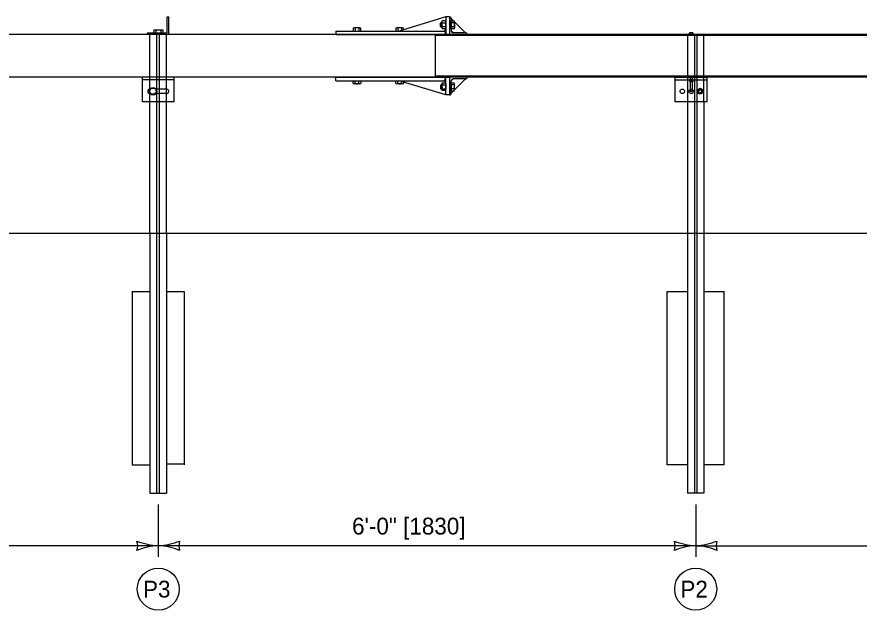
# Model space of a CAD drawing. Extents: x 49991.4 to 50021, y 49987.6 to 50011.4.
# Drawn here: x 50010.735 to 50013.742, y 49993.08 to 49995.198 of the extents above; entities that cross this region are included whole.
import ezdxf

# ---------------------------------------------------------------- set-up
doc = ezdxf.new("R2010")
doc.units = 0
for name, color, linetype in [('Level 1', 7, 'Continuous'), ('Level 2', 7, 'Continuous'), ('Level 3', 7, 'Continuous'), ('Level 4', 7, 'Continuous'), ('Level 63', 7, 'Continuous')]:
    doc.layers.add(name, color=color, linetype=linetype)

# ---------------------------------------------------------------- blocks, each defined once
blk = doc.blocks.new('HEX$NU')
at = {"layer": 'Level 63'}
for p, q in [((0, -0.325), (0, 0.325)), ((0.03, 0.433), (0.418, 0.433)), ((0.03, 0.216), (0.418, 0.216)), ((0.448, 0.325), (0.448, -0.325)), ((0.03, -0.216), (0.418, -0.216)), ((0.418, -0.433), (0.03, -0.433))]:
    blk.add_line(p, q, dxfattribs=at)
for centre, radius, start, end in [((0.21, 0.325), 0.21, 149.0201, 210.9799), ((0.796, 0), 0.796, 164.2217, 195.7782), ((0.238, 0.325), 0.21, 329.0201, 30.97992), ((-0.348, 0), 0.796, 344.2218, 15.77825), ((0.21, -0.325), 0.21, 149.0201, 210.9799), ((0.238, -0.325), 0.21, 329.0201, 30.97991)]:
    blk.add_arc(centre, radius, start, end, dxfattribs=at)
blk = doc.blocks.new('HEX$BO')
at = {"layer": 'Level 63'}
blk.add_lwpolyline([(0, 0.433), (-0.375, 0.2165), (-0.375, -0.2165), (0, -0.433), (0.375, -0.2165), (0.375, 0.2165)], close=True, dxfattribs=at)
blk.add_circle((0, 0), 0.25, dxfattribs=at)
for start, end in [(167.0572, 187.9055), (127.03, 148.675), (91.36985, 104.7376), (62.329189, 72.366658), (18.86795, 41.261061), (207.6209, 226.5812), (247.4266, 272.6797), (298.2529, 323.1939), (337.4806, 357.0806)]:
    blk.add_arc((0, 0), 0.2226, start, end, dxfattribs=at)

msp = doc.modelspace()

# ---------------------------------------------------------------- linework, layer by layer
at = {"layer": 'Level 1'}
for p, q in [((50011.2712, 49995.1981), (50011.2776, 49995.1981)), ((50011.2712, 49995.1411), (50011.2712, 49995.1981)), ((50011.2776, 49995.1348), (50011.2776, 49995.1981)), ((50012.2668, 49995.1981), (50012.1002, 49995.1474)), ((50012.2668, 49995.1981), (50012.2668, 49995.1348)), ((50012.2795, 49995.1981), (50012.2668, 49995.1981)), ((50012.2795, 49995.1981), (50012.2795, 49995.1348)), ((50012.2795, 49995.1981), (50012.2795, 49995.1981)), ((50012.2795, 49995.1981), (50012.2795, 49995.1981)), ((50012.2859, 49995.1917), (50012.3366, 49995.1411)), ((50012.2859, 49995.1917), (50012.2859, 49995.1474)), ((50011.2242, 49995.1523), (50011.2554, 49995.1523)), ((50011.2242, 49995.1523), (50011.2242, 49995.1411)), ((50011.231, 49995.1523), (50011.231, 49995.1411)), ((50011.2486, 49995.1523), (50011.2486, 49995.1411)), ((50011.2554, 49995.1523), (50011.2554, 49995.1411)), ((50011.9598, 49995.159), (50011.9392, 49995.159)), ((50011.9426, 49995.1579), (50011.9426, 49995.1474)), ((50011.9426, 49995.1579), (50011.9426, 49995.1474)), ((50011.9563, 49995.1579), (50011.9563, 49995.1474)), ((50012.1121, 49995.159), (50012.0915, 49995.159)), ((50012.1121, 49995.159), (50012.0915, 49995.159)), ((50012.0949, 49995.1579), (50012.0949, 49995.1474)), ((50012.0949, 49995.1579), (50012.0949, 49995.1474)), ((50012.1087, 49995.1579), (50012.1087, 49995.15)), ((50012.1087, 49995.1579), (50012.1087, 49995.15)), ((50012.1155, 49995.1521), (50012.1155, 49995.1579)), ((50012.1155, 49995.1521), (50012.1155, 49995.1579)), ((50012.2494, 49995.1775), (50012.2478, 49995.1759)), ((50012.2478, 49995.1633), (50012.2478, 49995.1759)), ((50012.2494, 49995.1617), (50012.2478, 49995.1633)), ((50012.2494, 49995.1775), (50012.2494, 49995.1617)), ((50012.2494, 49995.1775), (50012.2526, 49995.1775)), ((50012.2526, 49995.1759), (50012.2494, 49995.1759)), ((50012.2494, 49995.1633), (50012.2526, 49995.1633)), ((50012.2526, 49995.1617), (50012.2494, 49995.1617)), ((50012.2668, 49995.1538), (50012.2605, 49995.1474)), ((50012.2963, 49995.1764), (50012.2859, 49995.1764)), ((50012.2963, 49995.1627), (50012.2859, 49995.1627)), ((50012.2974, 49995.1799), (50012.2974, 49995.1593)), ((50012.2287, 49995.1348), (50001.2264, 49995.1348)), ((50011.2016, 49995.1348), (50011.2016, 49995.1411)), ((50011.2016, 49995.1411), (50011.2712, 49995.1411)), ((50011.8733, 49995.1474), (50011.8733, 49995.1348)), ((50011.8733, 49995.1474), (50012.2605, 49995.1474)), ((50011.8733, 49995.1348), (50012.2605, 49995.1348)), ((50015.8847, 49995.1348), (50012.2287, 49995.1348)), ((50012.2287, 49995.1348), (50012.2287, 49994.9829)), ((50012.2287, 49995.1348), (50012.2287, 49994.9829)), ((50012.2605, 49995.1474), (50012.2668, 49995.1411)), ((50012.2605, 49995.1348), (50012.2668, 49995.1411)), ((50012.2668, 49995.1348), (50012.2795, 49995.1348)), ((50012.343, 49995.1348), (50012.2795, 49995.1348)), ((50012.2922, 49995.1411), (50012.2859, 49995.1474)), ((50012.3366, 49995.1411), (50012.2922, 49995.1411)), ((50012.343, 49995.1348), (50012.343, 49995.1348)), ((50013.1479, 49995.1405), (50013.1376, 49995.1405)), ((50013.1479, 49995.1405), (50013.1376, 49995.1405)), ((50013.1393, 49995.14), (50013.1393, 49995.1348)), ((50013.1393, 49995.14), (50013.1393, 49995.1348)), ((50013.1462, 49995.14), (50013.1462, 49995.1348)), ((50013.1462, 49995.14), (50013.1462, 49995.1348)), ((50012.2287, 49994.9829), (50001.2264, 49994.9829)), ((50011.1828, 49994.8944), (50011.1828, 49994.9829)), ((50011.2968, 49994.9734), (50011.1828, 49994.9734)), ((50011.2968, 49994.8944), (50011.2968, 49994.9829)), ((50011.8733, 49994.9829), (50012.2605, 49994.9829)), ((50011.8733, 49994.9702), (50011.8733, 49994.9829)), ((50015.4023, 49994.9829), (50012.2287, 49994.9829)), ((50012.2605, 49994.9829), (50012.2668, 49994.9766)), ((50012.2605, 49994.9702), (50012.2668, 49994.9766)), ((50012.2668, 49994.9829), (50012.2795, 49994.9829)), ((50012.2668, 49994.9196), (50012.2668, 49994.9829)), ((50012.343, 49994.9829), (50012.2795, 49994.9829)), ((50012.2795, 49994.9829), (50012.2795, 49994.9196)), ((50012.2922, 49994.9766), (50012.2859, 49994.9702)), ((50012.2859, 49994.9259), (50012.3366, 49994.9766)), ((50012.3366, 49994.9766), (50012.2922, 49994.9766)), ((50012.343, 49994.9829), (50012.343, 49994.9829)), ((50013.0856, 49994.8943), (50013.0856, 49994.9829)), ((50013.0856, 49994.9829), (50013.1999, 49994.9829)), ((50013.0856, 49994.9734), (50013.1999, 49994.9734)), ((50013.1388, 49994.9829), (50013.1467, 49994.9829)), ((50013.1388, 49994.9829), (50013.1467, 49994.9829)), ((50013.1396, 49994.933), (50013.1396, 49994.9829)), ((50013.1459, 49994.9829), (50013.1459, 49994.933)), ((50013.1999, 49994.8943), (50013.1999, 49994.9829)), ((50011.8733, 49994.9702), (50012.2605, 49994.9702)), ((50011.9598, 49994.9587), (50011.9392, 49994.9587)), ((50011.9598, 49994.9587), (50011.9392, 49994.9587)), ((50011.9426, 49994.9598), (50011.9426, 49994.9702)), ((50011.9426, 49994.9598), (50011.9426, 49994.9702)), ((50011.9563, 49994.9598), (50011.9563, 49994.9702)), ((50011.9563, 49994.9598), (50011.9563, 49994.9702)), ((50012.1121, 49994.9587), (50012.0915, 49994.9587)), ((50012.0949, 49994.9598), (50012.0949, 49994.9702)), ((50012.0949, 49994.9598), (50012.0949, 49994.9702)), ((50012.2668, 49994.9196), (50012.1002, 49994.9702)), ((50012.1087, 49994.9598), (50012.1087, 49994.9677)), ((50012.1087, 49994.9598), (50012.1087, 49994.9677)), ((50012.1155, 49994.9656), (50012.1155, 49994.9598)), ((50012.1155, 49994.9656), (50012.1155, 49994.9598)), ((50012.2494, 49994.956), (50012.2478, 49994.9544)), ((50012.2478, 49994.9544), (50012.2478, 49994.9417)), ((50012.2494, 49994.9402), (50012.2478, 49994.9417)), ((50012.2494, 49994.9402), (50012.2494, 49994.956)), ((50012.2526, 49994.956), (50012.2494, 49994.956)), ((50012.2494, 49994.9544), (50012.2526, 49994.9544)), ((50012.2526, 49994.9417), (50012.2494, 49994.9417)), ((50012.2668, 49994.9639), (50012.2605, 49994.9702)), ((50012.2859, 49994.9259), (50012.2859, 49994.9702)), ((50012.2963, 49994.9549), (50012.2859, 49994.9549)), ((50012.2974, 49994.9378), (50012.2974, 49994.9584)), ((50013.1388, 49994.9663), (50013.1388, 49994.933)), ((50013.1467, 49994.933), (50013.1467, 49994.9663)), ((50011.2692, 49994.9402), (50011.2316, 49994.9402)), ((50011.2698, 49994.9244), (50011.2318, 49994.9244)), ((50012.2494, 49994.9402), (50012.2526, 49994.9402)), ((50012.2795, 49994.9196), (50012.2668, 49994.9196)), ((50012.2795, 49994.9196), (50012.2795, 49994.9196)), ((50012.2795, 49994.9196), (50012.2795, 49994.9196)), ((50012.2963, 49994.9412), (50012.2859, 49994.9412)), ((50013.1388, 49994.933), (50013.1396, 49994.9323)), ((50013.1388, 49994.933), (50013.1396, 49994.9323)), ((50013.1467, 49994.933), (50013.1388, 49994.933)), ((50013.1467, 49994.933), (50013.1388, 49994.933)), ((50013.1396, 49994.9323), (50013.1459, 49994.9323)), ((50013.1396, 49994.9323), (50013.1459, 49994.9323)), ((50013.1467, 49994.933), (50013.1459, 49994.9323)), ((50013.1467, 49994.933), (50013.1459, 49994.9323)), ((50011.2968, 49994.8944), (50011.1828, 49994.8944)), ((50011.21, 49994.4258), (50011.21, 49994.8943)), ((50011.2692, 49994.4258), (50011.2692, 49994.8943)), ((50013.1999, 49994.8943), (50013.0856, 49994.8943)), ((50013.129, 49994.8943), (50013.129, 49994.4259)), ((50013.1882, 49994.8943), (50013.1882, 49994.4259)), ((49999.8098, 49994.4259), (50016.5942, 49994.4259))]:
    msp.add_line(p, q, dxfattribs=at)
for points in [[(50012.2963, 49995.1559), (50012.2859, 49995.1559), (50012.2859, 49995.1833), (50012.2963, 49995.1833)], [(50011.9357, 49995.1579), (50011.9357, 49995.1474), (50011.9632, 49995.1474), (50011.9632, 49995.1579)], [(50011.9357, 49995.1579), (50011.9357, 49995.1474), (50011.9632, 49995.1474), (50011.9632, 49995.1579)], [(50012.088, 49995.1579), (50012.088, 49995.1474), (50012.1002, 49995.1474)], [(50012.088, 49995.1579), (50012.088, 49995.1474), (50012.1002, 49995.1474)], [(50013.1359, 49995.14), (50013.1359, 49995.1348), (50013.1496, 49995.1348), (50013.1496, 49995.14)], [(50013.1359, 49995.14), (50013.1359, 49995.1348), (50013.1496, 49995.1348), (50013.1496, 49995.14)], [(50011.9357, 49994.9598), (50011.9357, 49994.9702), (50011.9632, 49994.9702), (50011.9632, 49994.9598)], [(50011.9357, 49994.9598), (50011.9357, 49994.9702), (50011.9632, 49994.9702), (50011.9632, 49994.9598)], [(50012.088, 49994.9598), (50012.088, 49994.9702), (50012.1002, 49994.9702)], [(50012.088, 49994.9598), (50012.088, 49994.9702), (50012.1002, 49994.9702)], [(50012.2963, 49994.9618), (50012.2859, 49994.9618), (50012.2859, 49994.9344), (50012.2963, 49994.9344)]]:
    msp.add_lwpolyline(points, dxfattribs=at)
msp.add_lwpolyline([(50011.2146, 49994.9431), (50011.227, 49994.943), (50011.233, 49994.9322), (50011.2266, 49994.9216), (50011.2144, 49994.9218), (50011.2084, 49994.9325)], close=True, dxfattribs=at)
msp.add_circle((50011.2208, 49994.9322), 0.0135, dxfattribs=at)
for centre, start, end in [((50011.2097, 49994.9323), 88.9909, 270.2781), ((50011.2698, 49994.9323), 269.7219, 91.0091)]:
    msp.add_arc(centre, 0.00794, start, end, dxfattribs=at)
for centre, major_axis, start_param, end_param in [((50012.2795, 49995.1917), (-0.00635, 0), 3.141593, 4.712389), ((50012.2915, 49995.1799), (-0.00587, 0), 2.516161, 3.767024), ((50011.9392, 49995.1531), (-0.00587, 0), 4.086959, 5.337819), ((50011.9392, 49995.1531), (-0.00587, 0), 4.086959, 5.337819), ((50011.9495, 49995.1372), (-0.0218, 0), 4.391838, 5.03294), ((50011.9495, 49995.1372), (-0.0218, 0), 4.391838, 5.03294), ((50011.9598, 49995.1531), (-0.00587, 0), 4.086957, 5.337821), ((50012.0915, 49995.1531), (-0.00587, 0), 4.086959, 5.337819), ((50012.0915, 49995.1531), (-0.00587, 0), 4.086959, 5.337819), ((50012.1018, 49995.1372), (-0.0218, 0), 4.391838, 5.03294), ((50012.1018, 49995.1372), (-0.0218, 0), 4.391838, 5.03294), ((50012.1121, 49995.1531), (-0.00587, 0), 4.086957, 5.337821), ((50012.1121, 49995.1531), (-0.00587, 0), 4.086957, 5.337821), ((50012.2756, 49995.1696), (-0.0218, 0), 2.821042, 3.462143), ((50012.2915, 49995.1593), (-0.00587, 0), 2.516163, 3.767023), ((50012.2922, 49995.1474), (-0.00635, 0), 0, 1.570796), ((50012.3366, 49995.1348), (-0.00635, 0), 3.141593, 4.712389), ((50013.1376, 49995.1376), (-0.00293, 0), 4.086959, 5.337819), ((50013.1376, 49995.1376), (-0.00293, 0), 4.086959, 5.337819), ((50013.1427, 49995.1297), (-0.0109, 0), 4.391838, 5.03294), ((50013.1427, 49995.1297), (-0.0109, 0), 4.391838, 5.03294), ((50013.1479, 49995.1376), (-0.00293, 0), 4.086957, 5.337821), ((50013.1479, 49995.1376), (-0.00293, 0), 4.086957, 5.337821), ((50012.2922, 49994.9702), (-0.00635, 0), 4.712389, 6.283185), ((50012.3366, 49994.9829), (-0.00635, 0), 1.570796, 3.141593), ((50011.9392, 49994.9646), (-0.00587, 0), 0.945366, 2.196226), ((50011.9392, 49994.9646), (-0.00587, 0), 0.945366, 2.196226), ((50011.9495, 49994.9805), (-0.0218, 0), 1.250246, 1.891347), ((50011.9598, 49994.9646), (-0.00587, 0), 0.945365, 2.196228), ((50011.9598, 49994.9646), (-0.00587, 0), 0.945365, 2.196228), ((50012.0915, 49994.9646), (-0.00587, 0), 0.945366, 2.196226), ((50012.1018, 49994.9805), (-0.0218, 0), 1.250246, 1.891347), ((50012.1018, 49994.9805), (-0.0218, 0), 1.250246, 1.891347), ((50012.1121, 49994.9646), (-0.00587, 0), 0.945365, 2.196228), ((50012.1121, 49994.9646), (-0.00587, 0), 0.945365, 2.196228), ((50012.2915, 49994.9584), (-0.00587, 0), 2.516163, 3.767023), ((50012.2756, 49994.9481), (-0.0218, 0), 2.821042, 3.462143), ((50012.2795, 49994.9259), (-0.00635, 0), 1.570796, 3.141593), ((50012.2915, 49994.9378), (-0.00587, 0), 2.516161, 3.767024)]:
    msp.add_ellipse(centre, major_axis=major_axis, ratio=0.997137, start_param=start_param, end_param=end_param, dxfattribs=at)
for centre in [(50013.111, 49994.9323), (50013.1427, 49994.9323), (50013.1745, 49994.9323)]:
    msp.add_ellipse(centre, major_axis=(-0.00793, 0), ratio=0.997137, dxfattribs=at)
at = {"layer": 'Level 2'}
for centre in [(50011.2397, 49993.1553), (50013.1586, 49993.1553)]:
    msp.add_circle(centre, 0.075, dxfattribs=at)
at = {"layer": 'Level 3'}
for p, q in [((50011.2396, 49993.458), (50011.2396, 49993.2703)), ((50013.1586, 49993.458), (50013.1586, 49993.2703)), ((50011.2396, 49993.3103), (50009.4164, 49993.3103)), ((50013.1586, 49993.3103), (50011.2396, 49993.3103)), ((50013.1586, 49993.3103), (50015.7531, 49993.3103))]:
    msp.add_line(p, q, dxfattribs=at)
for centre, radius, start, end in [((50011.2488, 49993.5324), 0.2223, 247.456, 267.6395), ((50011.1114, 49993.3103), 0.0548, 342.1388, 17.8612), ((50011.2281, 49993.543), 0.233, 272.8273, 292.0772), ((50011.3678, 49993.3103), 0.0548, 162.1388, 197.8612), ((50013.1678, 49993.5324), 0.2223, 247.456, 267.6395), ((50013.0304, 49993.3103), 0.0548, 342.1388, 17.8612), ((50013.1471, 49993.543), 0.233, 272.8273, 292.0772), ((50013.2868, 49993.3103), 0.0548, 162.1388, 197.8612), ((50011.2511, 49993.0776), 0.233, 92.8273, 112.0772), ((50011.2304, 49993.0882), 0.2223, 67.456, 87.6395), ((50013.1701, 49993.0776), 0.233, 92.8273, 112.0772), ((50013.1494, 49993.0882), 0.2223, 67.456, 87.6395)]:
    msp.add_arc(centre, radius, start, end, dxfattribs=at)
at = {"layer": 'Level 4'}
for p, q in [((50011.21, 49994.8944), (50011.21, 49995.1348)), ((50011.235, 49993.498), (50011.235, 49995.1348)), ((50011.2442, 49993.498), (50011.2442, 49995.1348)), ((50011.2692, 49994.8944), (50011.2692, 49995.1348)), ((50015.8847, 49995.1316), (50012.2287, 49995.1316)), ((50013.129, 49995.1348), (50013.129, 49994.8943)), ((50013.154, 49995.1348), (50013.154, 49993.498)), ((50013.1632, 49995.1348), (50013.1632, 49993.498)), ((50013.1882, 49994.8943), (50013.1882, 49995.1348)), ((50015.8847, 49994.986), (50012.2287, 49994.986)), ((50011.21, 49994.4258), (50011.21, 49993.498)), ((50011.2692, 49994.4258), (50011.2692, 49993.498)), ((50013.129, 49994.4259), (50013.129, 49993.498)), ((50013.1882, 49994.4259), (50013.1882, 49993.498)), ((50011.1468, 49994.2178), (50011.21, 49994.2178)), ((50011.1468, 49994.2178), (50011.1468, 49993.5993)), ((50011.2692, 49994.2178), (50011.3324, 49994.2178)), ((50011.3324, 49994.2178), (50011.3324, 49993.5993)), ((50013.057, 49993.5993), (50013.057, 49994.2178)), ((50013.057, 49994.2178), (50013.129, 49994.2178)), ((50013.1882, 49994.2178), (50013.2602, 49994.2178)), ((50013.2602, 49993.5993), (50013.2602, 49994.2178)), ((50011.1468, 49993.5993), (50011.21, 49993.5993)), ((50011.2692, 49993.6027), (50011.3324, 49993.6027)), ((50013.129, 49993.5993), (50013.057, 49993.5993)), ((50013.2602, 49993.5993), (50013.1882, 49993.5993)), ((50011.21, 49993.498), (50011.2692, 49993.498)), ((50013.1882, 49993.498), (50013.129, 49993.498)), ((50013.1632, 49993.5055), (50013.1632, 49993.5055))]:
    msp.add_line(p, q, dxfattribs=at)

# ---------------------------------------------------------------- block references
at = {"layer": 'Level 1', "xscale": 0.031736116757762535}
for p, yscale in [((50012.2527, 49995.1701), -0.031645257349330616), ((50012.2527, 49994.9485), 0.031645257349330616)]:
    msp.add_blockref('HEX$NU', p, dxfattribs=dict(at, yscale=yscale))
at = {"layer": 'Level 1'}
for name, p, xscale, yscale, rotation in [('HEX$NU', (50013.143, 49994.9668), 0.015822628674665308, -0.015868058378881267, 90.00000000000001), ('HEX$BO', (50013.1747, 49994.9325), 0.025388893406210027, -0.025316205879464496, 180)]:
    msp.add_blockref(name, p, dxfattribs=dict(at, xscale=xscale, yscale=yscale, rotation=rotation))

# ---------------------------------------------------------------- texts
at = {"layer": 'Level 2'}
for s, height, p in [('6\'-0" [1830]', 0.060033, (50011.9316, 49993.3503)), ('P3', 0.06, (50011.1851, 49993.1253)), ('P2', 0.06, (50013.104, 49993.1253))]:
    msp.add_text(s, height=height, dxfattribs=at).set_placement(p)

doc.saveas('drawing.dxf')
